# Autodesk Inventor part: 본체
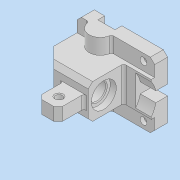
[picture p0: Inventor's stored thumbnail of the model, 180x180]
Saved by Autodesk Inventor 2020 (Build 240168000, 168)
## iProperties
Created: 2022-08
Part Number: 본체
Material: 일반
Document SubType Name: Modeling
Designer: MIRAE
Density: 1 g/cm^3
Appearance: 기본값
Author: MIRAE
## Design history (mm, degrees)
sketch "스케치1"
  geometry: L1 (-45, 38)-(45, 38); L2 (45, 38)-(45, -38); L3 (45, -38)-(-45, -38); L4 (-45, -38)-(-45, 38); L5 (-45, 38)-(45, -38); L6 (45, 38)-(-45, -38); 1 further point
  constraints: 12 end point, 2 midpoint, 2 parallel, 1 horizontal, 1 perpendicular
  dimensions: "d0" = 90 distance of L2.end L3.end; "d1" = 76 distance of L1.end L2.end
extrude "돌출1" new body sketch "스케치1" distance "d2" = 15; taper "d3" = 0 deg
sketch "스케치2"
  geometry: L1 (-45, 38)-(-45, -38) reference; L2 (-45, 20)-(13, 20); L3 (13, 20)-(13, -20); L4 (13, -20)-(-45, -20); L5 (-45, -20)-(-45, 20); L6 (-45, 0)-(64.688, 0); L7 (45, -38)-(45, 38) reference; 2 further points
  constraints: 10 end point, 2 horizontal, 2 midpoint, 2 parallel, 1 perpendicular, 1 point on line
  dimensions: "d4" = 40 distance between parallel lines of L4 L2; "d5" = 32 distance between parallel lines of L7 L3
extrude "돌출2" join sketch "스케치2" distance "d6" = 45; taper "d7" = 0 deg
chamfer "모따기1" distance "d8" = 18; stored, may be unused: second distance "d9" = 2, angle "d10" = 45 deg
sketch "스케치3"
  geometry: L1 (17, 8)-(37, 8); L2 (37, 8)-(37, -8.413); L3 (37, -8.413)-(17, -8.413); L4 (17, -8.413)-(17, 8); L5 (0, 0)-(90, 0) reference; L6 (27, 8)-(27, -18.381); L7 (0, 0)-(0, 15) reference; 1 further point
  constraints: 10 end point, 2 parallel, 1 horizontal, 1 midpoint, 1 perpendicular, 1 vertical
  dimensions: "d11" = 8 distance between parallel lines of L5 L1; "d12" = 27 distance between parallel lines of L7 L6; "d13" = 20 distance between parallel lines of L4 L2
extrude "돌출3" cut sketch "스케치3" extent not by distance; stored distance "d14" = 0; taper "d15" = 0 deg
sketch "스케치4"
  geometry: L1 (37, -7)-(17, -7) reference; L2 (27, -7)-(27, 0); L3 (0, 0)-(90, 0) reference; A1 r 13 centre (27, 0) between (40, 0) and (14, 0); 1 further point
  constraints: 3 point on line, 2 end point, 2 point on circle, 1 centre point, 1 coincident, 1 midpoint, 1 vertical
  dimensions: "d16" = 26 diameter of A1
extrude "돌출4" join sketch "스케치4" stored distance "d17" = 45; taper "d18" = 0 deg
sketch "스케치5"
  geometry: L1 (13, 20)-(13, -20) reference; L2 (45, -38)-(45, 38) reference; L3 (13, 20)-(45, 20); L4 (45, 20)-(45, -20); L5 (45, -20)-(13, -20); L6 (13, -20)-(13, 20); L7 (-27, -20)-(13, -20) reference; 2 further points
  constraints: 8 end point, 2 parallel, 2 point on line, 1 horizontal, 1 perpendicular
extrude "돌출5" join sketch "스케치5" distance "d19" = 4; taper "d20" = 0 deg
sketch "스케치6"
  geometry: L1 (16, 90)-(-8, 90); L2 (-8, 90)-(-8, 52.862); L3 (-8, 52.862)-(16, 52.862); L4 (16, 52.862)-(16, 90); L5 (-13, 60)-(27, 60) reference; L6 (-13, 19)-(-13, 60) reference; 1 further point
  constraints: 8 end point, 2 parallel, 1 horizontal, 1 perpendicular
  dimensions: "d21" = 5 distance between parallel lines of L6 L2; "d22" = 24 distance between parallel lines of L4 L2; "d23" = 30 distance between parallel lines of L5 L1
extrude "돌출6" join sketch "스케치6" stored distance "d24" = 15; taper "d25" = 0 deg
chamfer "모따기2" distance "d26" = 5; stored, may be unused: second distance "d27" = 2, angle "d28" = 45 deg
sketch "스케치7"
  geometry: L1 (60, -18)-(60, 58) reference; 4 further points
  constraints: 2 midpoint, 1 horizontal alignment
  dimensions: "d30" = 42 distance from line of L1 point (18, 20)
hole "구멍1" sketch "스케치7" at (18, 20) diameter "d31" = 20; stored, may be unused: countersink angle "d35" = 90 deg, drill point angle "d37" = 118 deg; dims "d32" = 3, "d33" = 29, "d34" = 7, "d36" = 8
sketch "스케치8"
  geometry: C1 r 10 at (-42, 38) reference; C2 r 29 at (-42, 38); 1 further point
  constraints: 1 centre point, 1 coincident
  dimensions: "d38" = 58 diameter of C2
extrude "돌출7" cut sketch "스케치8" distance "d39" = 18; taper "d40" = 0 deg
sketch "스케치9"
  geometry: L1 (8.301, 32)-(-17.655, 32); L2 (-17.655, 32)-(-17.655, 44); L3 (-17.655, 44)-(8.301, 44); L4 (8.301, 44)-(8.301, 32); L5 (0, 0)-(0, 76) reference; 3 further points
  constraints: 8 end point, 2 midpoint, 2 parallel, 1 horizontal, 1 horizontal alignment, 1 perpendicular
  dimensions: "d41" = 12 distance between parallel lines of L1 L3
extrude "돌출8" cut sketch "스케치9" distance "d42" = 18; taper "d43" = 0 deg
sketch "스케치10"
  geometry: L1 (-6, 56.5)-(-6, 27.5) reference; L2 (-6, 42)-(51.052, 42); L3 (-8, 85)-(-8, 60) reference; C1 r 4 at (4, 77); 1 further point
  constraints: 2 end point, 1 centre point, 1 horizontal, 1 midpoint
  dimensions: "d44" = 12 distance from line of L3 C1.centre; "d45" = 8 diameter of C1; "d46" = 35 distance from line of L2 C1.centre
extrude "돌출9" cut sketch "스케치10" extent not by distance; stored distance "d47" = 7.5; taper "d48" = 0 deg
sketch "스케치11"
  geometry: L1 (45, -38)-(45, -20) reference; L2 (-45, 0)-(72.621, 0); A1 r 10 centre (-45, 0) between (-45, -10) and (-45, 10) reference; 2 further points
  constraints: 2 end point, 1 horizontal
  dimensions: "d49" = 13 distance from line of L1 point (32, -30); "d50" = 30 distance from line of point (32, -30) L2
hole "구멍2" sketch "스케치11" at (32, -30) diameter "d51" = 4.5; stored, may be unused: countersink angle "d55" = 90 deg, drill point angle "d57" = 118 deg; dims "d52" = 3, "d53" = 8, "d54" = 4.4, "d56" = 8
chamfer "모따기3" distance "d58" = 1; stored, may be unused: second distance "d59" = 2, angle "d60" = 45 deg
chamfer "모따기4" distance "d61" = 1; stored, may be unused: second distance "d62" = 2, angle "d63" = 45 deg
chamfer "모따기5" distance "d64" = 5; stored, may be unused: second distance "d65" = 2, angle "d66" = 45 deg
fillet "모깎기1" dims "d67" = 3
chamfer "모따기6" distance "d68" = 5; stored, may be unused: second distance "d69" = 2, angle "d70" = 45 deg
fillet "모깎기2" dims "d71" = 3
sketch "스케치12"
  geometry: L1 (58, 7)-(58, 40) reference; L2 (58, 45)-(18, 45) reference; 2 further points
  constraints: 1 other
  dimensions: "d72" = 26 distance from line of L1 point (32, 27); "d73" = 18 distance from line of L2 point (32, 27)
feature "엠보싱1" sketch "스케치12" dims "d0" = 90, "d1" = 76, "d10" = 45 deg, "d74" = 0.5, "d75" = 0
node "솔리드1"
mirror "미러1"
feature "A9D066F2-1C7D-4E18-AEED-F7BC21143FA4" dims "d31" = 20, "d32" = 3, "d33" = 29, "d34" = 7, "d35" = 90 deg, "d36" = 8, "d37" = 118 deg
